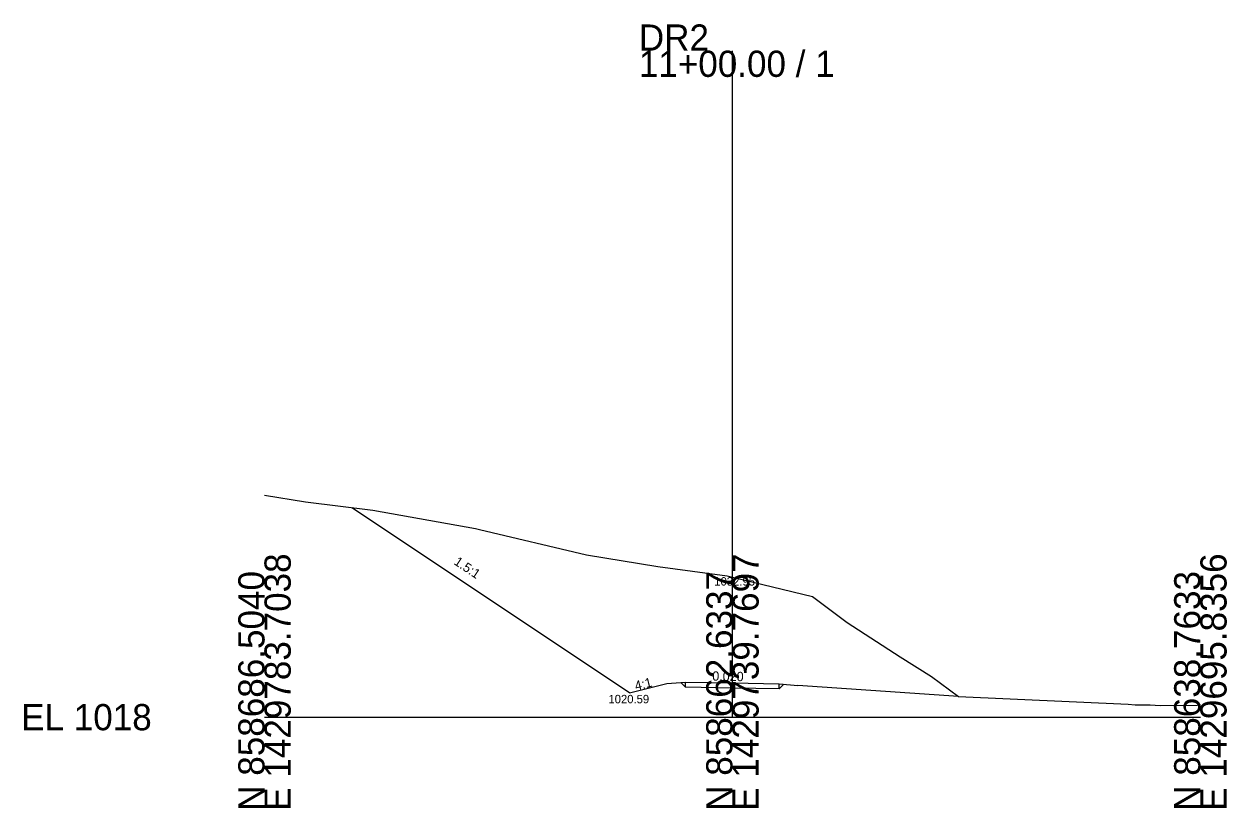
# Model space of a CAD drawing. Extents: x -26 to 103, y -10 to 3026.
# Drawn here: x -25.7 to 102.8, y 1990.3 to 2074 of the extents above; entities that cross this region are included whole.
import ezdxf

# ---------------------------------------------------------------- set-up
doc = ezdxf.new("R2010")
doc.units = 0
for name, color, linetype in [('Default', 7, 'Continuous'), ('Exist Cross Section Cell', 7, 'Continuous'), ('Exist XS Center Line Elevation Label', 7, 'Continuous'), ('Exist XS Ground Line', 7, 'Continuous'), ('Prop CMT Pvmt Surface', 7, 'Continuous'), ('Prop CMT Shld Paved Course 1', 7, 'Continuous'), ('Prop CMT Slope Grass', 7, 'Continuous'), ('Prop CMT Subgrade Earthwork', 7, 'Continuous'), ('Prop CMT Template Flag', 7, 'Continuous'), ('Prop XS SE Text', 7, 'Continuous'), ('Prop XS Side Slope Text', 7, 'Continuous')]:
    doc.layers.add(name, color=color, linetype=linetype)

msp = doc.modelspace()

# ---------------------------------------------------------------- linework, layer by layer
at = {"layer": 'Exist Cross Section Cell'}
for p, q in [((50, 2000), (50, 2071.17)), ((0, 2000), (50, 2000)), ((50, 2000), (100, 2000))]:
    msp.add_line(p, q, dxfattribs=at)
at = {"layer": 'Exist XS Ground Line'}
msp.add_lwpolyline([(0, 2023.72), (4.39, 2022.98), (11.56, 2022.09), (22.53, 2020.16), (22.99, 2020.05), (34.41, 2017.33), (42.03, 2016.08), (49.42, 2015.09), (50, 2014.95), (58.56, 2012.87), (62.27, 2010.12), (67.94, 2006.43), (71.26, 2004.33), (74.17, 2002.21), (92.3, 2001.39), (93.04, 2001.32), (93.71, 2001.32), (94.62, 2001.32), (95.7, 2001.24), (99.67, 2001.29), (100, 2001.3)], dxfattribs=at)
at = {"layer": 'Prop CMT Pvmt Surface'}
for p, q in [((45, 2003.75), (50, 2003.65)), ((50, 2003.65), (55, 2003.55))]:
    msp.add_line(p, q, dxfattribs=at)
at = {"layer": 'Prop CMT Shld Paved Course 1'}
for points in [[(45, 2003.21), (45, 2003.75)], [(55, 2003.01), (55, 2003.55)]]:
    msp.add_lwpolyline(points, dxfattribs=at)
at = {"layer": 'Prop CMT Slope Grass'}
for p, q in [((39, 2002.59), (9.34, 2022.36)), ((39, 2002.59), (43, 2003.59)), ((43, 2003.59), (45, 2003.75)), ((55, 2003.55), (57, 2003.39)), ((74.17, 2002.21), (57, 2003.39))]:
    msp.add_line(p, q, dxfattribs=at)
at = {"layer": 'Prop CMT Subgrade Earthwork'}
for points in [[(45, 2003.21), (44.5, 2003.71)], [(55, 2003.01), (55.5, 2003.51)]]:
    msp.add_lwpolyline(points, dxfattribs=at)
at = {"layer": 'Prop CMT Template Flag'}
for p, q in [((50, 2003.11), (45, 2003.21)), ((55, 2003.01), (50, 2003.11))]:
    msp.add_line(p, q, dxfattribs=at)

# ---------------------------------------------------------------- texts
at = {"layer": 'Default'}
msp.add_text('1020.59', height=0.9, dxfattribs=at).set_placement((36.75, 2001.48))
at = {"layer": 'Exist Cross Section Cell'}
for s, p in [('DR2', (40, 2071.17)), ('11+00.00 / 1', (40, 2068.37)), ('EL 1018', (-26, 1998.6))]:
    msp.add_text(s, height=2.8, dxfattribs=at).set_placement(p)
for s, p in [('E 1429783.7038', (2.8, 1990)), ('E 1429739.7697', (52.8, 1990)), ('E 1429695.8356', (102.8, 1990)), ('N 858686.5040', (0, 1990)), ('N 858662.6337', (50, 1990)), ('N 858638.7633', (100, 1990))]:
    msp.add_text(s, height=2.8, rotation=90, dxfattribs=at).set_placement(p)
at = {"layer": 'Exist XS Center Line Elevation Label'}
msp.add_text('1032.95', height=0.9, dxfattribs=at).set_placement((48.06, 2014.05))
at = {"layer": 'Prop XS SE Text'}
msp.add_text('0.020', height=1, rotation=358.8542, dxfattribs=at).set_placement((47.84, 2003.9))
at = {"layer": 'Prop XS Side Slope Text'}
for s, rotation, p in [('1.5:1', 326.3099, (20.16, 2016.38)), ('4:1', 14.0362, (39.69, 2002.83))]:
    msp.add_text(s, height=1, rotation=rotation, dxfattribs=at).set_placement(p)

doc.saveas('drawing.dxf')
